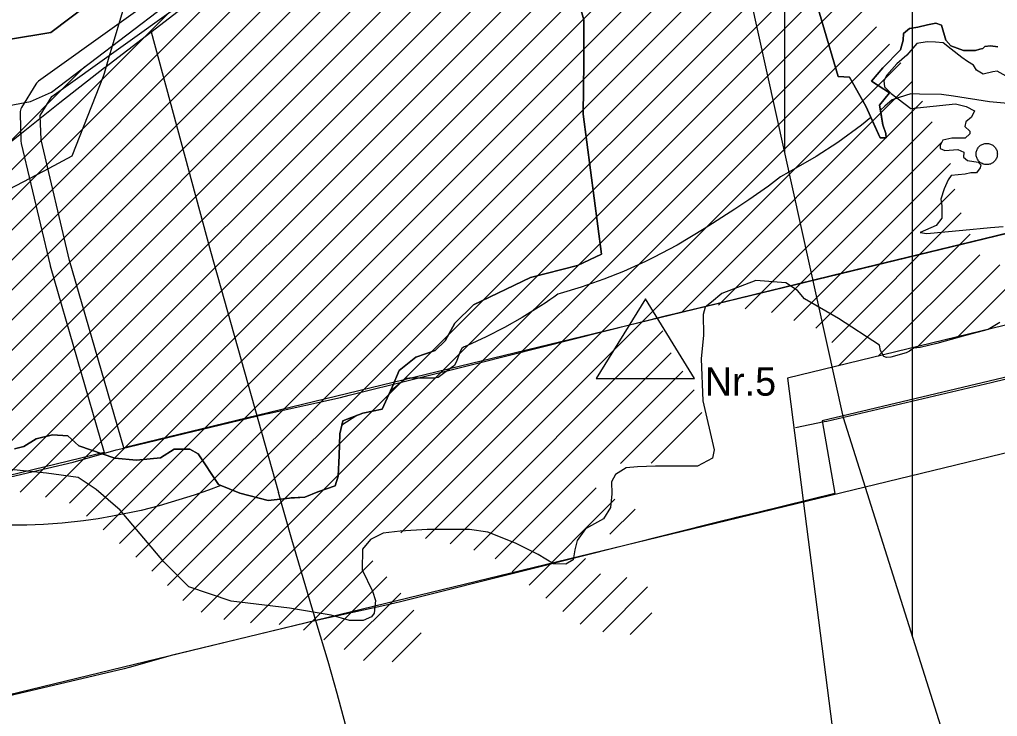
# Model space of a CAD drawing. Extents: x 468834 to 503362, y 294936 to 320859.
# Drawn here: x 481784 to 482703, y 305401 to 306056 of the extents above; entities that cross this region are included whole.
import ezdxf

# ---------------------------------------------------------------- set-up
doc = ezdxf.new("R2010")
doc.units = 0
for name, color, linetype in [('1020101_TIN11_plūdu riska teritorija', 7, 'Continuous'), ('1020103_TIN13_teritorijas ar augstu gruntsudens limeni', 7, 'Continuous'), ('1020700_TIN7_nacionalas_un_vietejas_nozimes_infrastrukturas_attistibas_teritorijas', 7, 'Continuous'), ('7311020201_par 1000 hektāriem lielākas dabiskas ūdenstilpes vides un dabas resursu aizsardzības aizsargjoslas teritorija lauku apvidos', 7, 'Continuous'), ('7311020400_applūstošā (10% applūduma varbūtība) teritorija', 7, 'Continuous'), ('7311090700_stingra režīma vides un dabas resursu aizsardzības aizsargjoslas teritorija ap pazemes ūdens ņemšanas vietu', 7, 'Continuous'), ('7312030301_ekspluatācijas aizsargjoslas teritorija gar valsts galvenajiem autoceļiem lauku apvidos', 7, 'Continuous'), ('7312070202_navigācijas tehniskā līdzekļa aviācijas gaisa kuģu lidojumu drošības nodrošināšanai tālās ietekmes zona', 7, 'Continuous'), ('7313040300_dabas lieguma dabas lieguma zonas teritorija', 7, 'Continuous'), ('7313040700_dabas lieguma sezonas lieguma teritorija', 7, 'Continuous'), ('aizkrāsojums-lidlauka tālās ietekmes zona', 7, 'Continuous'), ('aizkrāsojums-poldera teritorija', 7, 'Continuous'), ('aizkrāsojums_applūstošā teritorija', 7, 'Continuous'), ('Dabas lieguma robeža', 7, 'Continuous'), ('Koplietošanas novadgrāvis', 7, 'Continuous'), ('Polderu_baseini', 7, 'Continuous'), ('Potenciāli piesārņota vieta', 7, 'Continuous'), ('Teksts', 7, 'Continuous')]:
    doc.layers.add(name, color=color, linetype=linetype)

msp = doc.modelspace()

# ---------------------------------------------------------------- linework, layer by layer
at = {"layer": '1020101_TIN11_plūdu riska teritorija'}
for points in [[(482711.03, 306002.85), (482702.68, 306007.58), (482698.57, 306006.82), (482689.52, 306004.83), (482683.41, 306008.57), (482680.42, 306013.29), (482674.78, 306016.55), (482669.46, 306020.55), (482659.33, 306028.17), (482651.9, 306034.19), (482644.86, 306034.99), (482636.92, 306035.13), (482627.06, 306033.44), (482617.73, 306022.73), (482608.35, 306014.61), (482598.9, 306003.87), (482596.11, 305998.38), (482596.7, 305992.96), (482603, 305986.67), (482621.69, 305972.56), (482663.67, 305976.9), (482673.43, 305974.49), (482681.26, 305970.32), (482678.51, 305964.24), (482673.19, 305959.99), (482672.35, 305955.59), (482677.01, 305951.2), (482677.09, 305948.62), (482672.65, 305944.49), (482660.12, 305944.6), (482651.62, 305942.72), (482649.1, 305937.78), (482649.1, 305934.98), (482653.4, 305932.94), (482665.6, 305933.85), (482671.24, 305931.54), (482671.19, 305926.59), (482674.69, 305923.63), (482684.78, 305922.13), (482687.33, 305919.6), (482686.63, 305916.67), (482683.33, 305912.03), (482677.91, 305912.03), (482672.49, 305910.92), (482659.45, 305909.61), (482656.53, 305905.4), (482652.85, 305897.08), (482649.82, 305887.23), (482650.58, 305881.12), (482650.58, 305869.46), (482645.23, 305862.39), (482630.31, 305855.84), (482636.66, 305854.86), (482670.47, 305858.17), (482696.33, 305860.69), (482708.26, 305861.54)], [(482705.33, 305771.2), (482694.3, 305764.59), (482672.87, 305758.99), (482646.02, 305751.71), (482630.48, 305747.68), (482624.09, 305747.18), (482620.22, 305744.36), (482617.2, 305742.93), (482602.62, 305738.8), (482598.71, 305738.4), (482596.04, 305739.5), (482593.13, 305745.13), (482591.95, 305750.12), (482553.54, 305775.09), (482521.62, 305793.63), (482514.87, 305801.45), (482504.04, 305808.54), (482475.69, 305810.67), (482443.98, 305798.57), (482434.25, 305790.56), (482428.26, 305785.86), (482426.15, 305778.75), (482426.51, 305759.3), (482424.33, 305737.23), (482426, 305697.6), (482436.52, 305651.76), (482435.01, 305643.68), (482420.82, 305636.14), (482405.62, 305636.14), (482381.33, 305636.14), (482364.55, 305635.66), (482353.81, 305634.56), (482343.81, 305628.29), (482340.21, 305621.6), (482340.31, 305610.3), (482339.1, 305597.48), (482332.68, 305586.73), (482315.62, 305577.43), (482307.86, 305566.55), (482305.67, 305557.52), (482304.22, 305548.3), (482297.1, 305544.25), (482285.44, 305544.41), (482271.04, 305553.31), (482249.76, 305563.8), (482223.99, 305574.2), (482206.73, 305576.87), (482166.94, 305576.87), (482141.49, 305575.2), (482125.41, 305573.26), (482113.63, 305567.42), (482106.15, 305558.2), (482105.62, 305538.75), (482115.31, 305518.86), (482118.12, 305510.04), (482117.13, 305498.21), (482114.36, 305494.51), (482106.75, 305491.22), (482093.91, 305491.22), (482076.54, 305496.32), (482037.39, 305502.9), (481982.64, 305509.45), (481942.65, 305522.91), (481919.07, 305546.48), (481878.26, 305594.83), (481855.53, 305614.21), (481838.59, 305625.51), (481808.76, 305629.68), (481775.19, 305633.01)]]:
    msp.add_lwpolyline(points, dxfattribs=at)
at = {"layer": '1020103_TIN13_teritorijas ar augstu gruntsudens limeni'}
for p, q in [((481863.31, 306005.69), (481867.18, 306018.76)), ((481863.31, 306005.69), (481867.18, 306018.76)), ((481806.01, 305913.61), (481811.43, 305916.46)), ((481806.01, 305913.61), (481811.43, 305916.46))]:
    msp.add_line(p, q, dxfattribs=at)
for points in [[(481867.18, 306018.76), (481884.36, 306076.83), (481892.2, 306087.81)], [(481867.18, 306018.76), (481884.36, 306076.83), (481892.2, 306087.81)], [(481811.43, 305916.46), (481833.17, 305927.88), (481862.48, 306002.88), (481863.31, 306005.69)], [(481811.43, 305916.46), (481833.17, 305927.88), (481862.48, 306002.88), (481863.31, 306005.69)], [(481678.77, 305886.85), (481691.44, 305885.69), (481747.15, 305889.11), (481747.88, 305889.67), (481749.12, 305889.52), (481749.39, 305889.48), (481749.57, 305889.25), (481761, 305889.95), (481806.01, 305913.61)], [(481678.77, 305886.85), (481691.44, 305885.69), (481747.15, 305889.11), (481747.88, 305889.67), (481749.12, 305889.52), (481749.39, 305889.48), (481749.57, 305889.25), (481761, 305889.95), (481806.01, 305913.61)]]:
    msp.add_lwpolyline(points, dxfattribs=at)
at = {"layer": '1020700_TIN7_nacionalas_un_vietejas_nozimes_infrastrukturas_attistibas_teritorijas'}
for points in [[(481830.66, 305829.5), (481803.8, 305943.01), (481803.08, 305965.99), (481813.98, 305983.7), (482118.6, 306201.91), (482529.42, 306297.65), (482530.71, 306297.78), (482531.21, 306297.88), (482541.24, 306299.83), (482555.97, 306302.71), (482560.88, 306303.67), (482617.58, 306314.75), (482622.01, 306315.25), (482650.04, 306318.47), (482657.91, 306319.37), (482786.24, 306266.92)], [(481830.66, 305829.5), (481803.8, 305943.01), (481803.08, 305965.99), (481813.98, 305983.7), (482118.6, 306201.91), (482529.42, 306297.65), (482530.71, 306297.78), (482531.21, 306297.88), (482541.24, 306299.83), (482555.97, 306302.71), (482560.88, 306303.67), (482617.58, 306314.75), (482622.01, 306315.25), (482650.04, 306318.47), (482657.91, 306319.37), (482786.24, 306266.92)], [(482109.07, 306218.46), (481801.36, 305998.04), (481800.39, 305997.24), (481799.53, 305996.32), (481798.8, 305995.29), (481785.4, 305973.52), (481784.77, 305972.3), (481784.31, 305970.99), (481784.06, 305969.63), (481784, 305968.25), (481784.84, 305941.45), (481784.98, 305940.1), (481785.09, 305939.56), (481812.23, 305824.9), (481812.35, 305824.44), (481863.18, 305648.97), (481390.71, 305534.31)], [(482109.07, 306218.46), (481801.36, 305998.04), (481800.39, 305997.24), (481799.53, 305996.32), (481798.8, 305995.29), (481785.4, 305973.52), (481784.77, 305972.3), (481784.31, 305970.99), (481784.06, 305969.63), (481784, 305968.25), (481784.84, 305941.45), (481784.98, 305940.1), (481785.09, 305939.56), (481812.23, 305824.9), (481812.35, 305824.44), (481863.18, 305648.97), (481390.71, 305534.31)], [(482933.4, 305908.71), (481881.66, 305653.46), (481830.66, 305829.5)], [(482933.4, 305908.71), (481881.66, 305653.46), (481830.66, 305829.5)], [(481665.41, 305395.17), (482835.74, 305679.21)], [(481665.41, 305395.17), (482835.74, 305679.21)]]:
    msp.add_lwpolyline(points, dxfattribs=at)
at = {"layer": '7311020201_par 1000 hektāriem lielākas dabiskas ūdenstilpes vides un dabas resursu aizsardzības aizsargjoslas teritorija lauku apvidos'}
msp.add_lwpolyline([(482729.76, 305975.58), (482695.36, 305978.75), (482661.74, 305984.19), (482650.51, 305985.71), (482629.8, 305986.11), (482621.58, 305986.3), (482610.66, 305982.83), (482603.93, 305980.62), (482597.24, 305974.62), (482592.97, 305971.08), (482595.28, 305957.13), (482598.18, 305949.03), (482598.32, 305944.95), (482592.64, 305944.95), (482584.08, 305963.91), (482575.32, 305956.88), (482552.95, 305940.65), (482532.46, 305927.31), (482506.71, 305912.56), (482498.89, 305908.24), (482487.7, 305899.59), (482469.27, 305886.49), (482456.22, 305877.76), (482427.3, 305859.29), (482401.99, 305844.09), (482379.74, 305832.4), (482372.08, 305828.56), (482351.36, 305819.35), (482332.91, 305812.13), (482311.49, 305804.65), (482291.84, 305798.62), (482289.66, 305797.82), (482285.99, 305795.23), (482282.09, 305792.52), (482277.63, 305789.61), (482273.59, 305786.97), (482255.97, 305776.07), (482239.44, 305766.74), (482222.22, 305757.86), (482204.62, 305749.64), (482201.05, 305748.01), (482199.29, 305746.87), (482197.81, 305744.22), (482194.29, 305734.67), (482192.09, 305730.7), (482190.62, 305729.62), (482177, 305719.63), (482173.27, 305719), (482168.69, 305719), (482150.12, 305719), (482147.05, 305718.6), (482144.57, 305716.78), (482131.92, 305706.48), (482124.46, 305689.76), (482106.36, 305686.02), (482100.83, 305683.9), (482086.63, 305674.73), (482084.64, 305666.53), (482083.96, 305646.29), (482083.21, 305626.83), (482080.29, 305617.83), (482064.15, 305612.14), (482051.77, 305607.17), (482038.93, 305606.36), (482037.33, 305606.26), (482018.78, 305604.09), (482017.47, 305603.94), (481990.54, 305611), (481972.89, 305618.14), (481961.12, 305613.69), (481947.66, 305609), (481926.2, 305602.32), (481914.69, 305598.86), (481897.76, 305594.71), (481871.07, 305589.15), (481857.57, 305586.8), (481843.67, 305585), (481823.61, 305582.74), (481806.24, 305581.52), (481790.28, 305580.79), (481764.94, 305580.7)], dxfattribs=at)
at = {"layer": '7311020400_applūstošā (10% applūduma varbūtība) teritorija'}
for points in [[(482703.36, 306030.36), (482696.35, 306031.51), (482691.26, 306030.84), (482689.37, 306028.99), (482686.44, 306028.14), (482682.39, 306026.94), (482677.83, 306027.08), (482671.18, 306027.02), (482659.13, 306031.37), (482654.45, 306036.67), (482650.33, 306050.84), (482644.93, 306052.72), (482637.2, 306051.14), (482628.24, 306048.8), (482620.32, 306047.64), (482614.63, 306042.84), (482614.42, 306036.62), (482611.74, 306027.6), (482595.12, 306010.82), (482584.58, 305998.33), (482601.62, 305987.16), (482592.19, 305975.78), (482595.28, 305957.13), (482598.18, 305949.03), (482598.32, 305944.95), (482592.64, 305944.95), (482579.27, 305974.57), (482564.02, 306001.95), (482553.24, 306002.66), (482485.77, 306231.42)], [(482304.43, 306089.91), (482313.99, 306055.97), (482313.99, 306015.34), (482313.51, 305967.06), (482330.61, 305835.58), (482308.2, 305824.83), (482263.99, 305813.57), (482210.45, 305788.07), (482192.97, 305770.71), (482183.69, 305754.05), (482174.18, 305744.91), (482156.25, 305738.81), (482140.38, 305726.36), (482133.76, 305710.62), (482124.46, 305689.76), (482106.36, 305686.02), (482087.63, 305678.84), (482084.64, 305666.53), (482083.96, 305646.29), (482083.21, 305626.83), (482080.29, 305617.83), (482064.15, 305612.14), (482051.77, 305607.17), (482037.33, 305606.26), (482017.47, 305603.94), (481990.54, 305611), (481970.56, 305619.08), (481951.51, 305647.84), (481943.56, 305652.41), (481929.05, 305652.41), (481916.08, 305643.99), (481893.45, 305642.03), (481873.08, 305643.86), (481839.26, 305655.26), (481829.07, 305664.83), (481814.61, 305665.85), (481799.33, 305661.98), (481787.44, 305654.85), (481778.7, 305652.71)]]:
    msp.add_lwpolyline(points, dxfattribs=at)
at = {"layer": '7311090700_stingra režīma vides un dabas resursu aizsardzības aizsargjoslas teritorija ap pazemes ūdens ņemšanas vietu'}
msp.add_lwpolyline([(482702.91, 305929.71), (482702.87, 305928.84), (482702.76, 305927.97), (482702.57, 305927.12), (482702.31, 305926.29), (482701.97, 305925.48), (482701.57, 305924.71), (482701.1, 305923.97), (482700.57, 305923.28), (482699.98, 305922.64), (482699.34, 305922.05), (482698.65, 305921.52), (482697.91, 305921.05), (482697.14, 305920.65), (482696.33, 305920.31), (482695.5, 305920.05), (482694.65, 305919.86), (482693.78, 305919.75), (482692.91, 305919.71), (482692.04, 305919.75), (482691.17, 305919.86), (482690.32, 305920.05), (482689.49, 305920.31), (482688.68, 305920.65), (482687.91, 305921.05), (482687.17, 305921.52), (482686.48, 305922.05), (482685.84, 305922.64), (482685.25, 305923.28), (482684.72, 305923.97), (482684.25, 305924.71), (482683.85, 305925.48), (482683.51, 305926.29), (482683.25, 305927.12), (482683.06, 305927.97), (482682.95, 305928.84), (482682.91, 305929.71), (482682.95, 305930.58), (482683.06, 305931.45), (482683.25, 305932.3), (482683.51, 305933.13), (482683.85, 305933.94), (482684.25, 305934.71), (482684.72, 305935.45), (482685.25, 305936.14), (482685.84, 305936.78), (482686.48, 305937.37), (482687.17, 305937.9), (482687.91, 305938.37), (482688.68, 305938.77), (482689.49, 305939.11), (482690.32, 305939.37), (482691.17, 305939.56), (482692.04, 305939.67), (482692.91, 305939.71), (482693.78, 305939.67), (482694.65, 305939.56), (482695.5, 305939.37), (482696.33, 305939.11), (482697.14, 305938.77), (482697.91, 305938.37), (482698.65, 305937.9), (482699.34, 305937.37), (482699.98, 305936.78), (482700.57, 305936.14), (482701.1, 305935.45), (482701.57, 305934.71), (482701.97, 305933.94), (482702.31, 305933.13), (482702.57, 305932.3), (482702.76, 305931.45), (482702.87, 305930.58)], close=True, dxfattribs=at)
at = {"layer": '7312030301_ekspluatācijas aizsargjoslas teritorija gar valsts galvenajiem autoceļiem lauku apvidos'}
for points in [[(483411.74, 305886.23), (482538.33, 305678.85), (482549.99, 305610.47), (482477.55, 305592.8), (482456.06, 305587.55), (482455.26, 305587.36), (482441.16, 305584.05), (482263.15, 305539.15), (482141.83, 305508.87), (482132.41, 305506.52), (482130.45, 305506.05), (482129.71, 305505.88), (482061.12, 305490.77), (481927.41, 305458.67), (481886.53, 305447), (481881.91, 305445.8), (481831.56, 305434), (481693.81, 305401.61)], [(481647.17, 305596.1), (481785.84, 305628.7), (481833.93, 305639.98), (481874.55, 305651.57), (481878.85, 305652.7), (482015.34, 305685.46), (482016.43, 305685.72), (482017.17, 305685.89), (482085.32, 305700.9), (482093.4, 305702.92), (482214.48, 305733.13), (482393.02, 305778.17), (482394.59, 305778.55), (482409.07, 305781.96), (482430.15, 305787.1), (482559.44, 305818.63), (482677.18, 305847.12), (482727.6, 305859.22)]]:
    msp.add_lwpolyline(points, dxfattribs=at)
at = {"layer": '7312070202_navigācijas tehniskā līdzekļa aviācijas gaisa kuģu lidojumu drošības nodrošināšanai tālās ietekmes zona'}
msp.add_lwpolyline([(485919.77, 299448.94), (484759.97, 300960.42), (484056.87, 302064.06), (483452.63, 303224.79), (482951.86, 304433.76), (482558.36, 305681.78), (482275.13, 306959.34), (482104.33, 308256.73), (482047.25, 309564.06), (482104.33, 310871.4), (482275.13, 312168.79), (482558.36, 313446.35), (482951.86, 314694.37), (483452.63, 315903.34), (483846.7, 316660.32)], dxfattribs=at)
at = {"layer": '7313040300_dabas lieguma dabas lieguma zonas teritorija'}
msp.add_lwpolyline([(483262.45, 306442.89), (483166.01, 306341.72), (483118.73, 306397.51), (482845.46, 306301.06), (482660.12, 306396.56), (482578.8, 306371.03), (482483.3, 306354.01), (482166.53, 306269.85), (482094.67, 306254.72), (482009.57, 306192.32), (481812.89, 306043.86), (481773.17, 306037.24), (481710.77, 306102.49), (481645.52, 306141.25), (481387.38, 306316.19), (481144.25, 306369.79), (481040.27, 306354.7), (480542.98, 305757.35)], dxfattribs=at)
at = {"layer": '7313040700_dabas lieguma sezonas lieguma teritorija'}
msp.add_lwpolyline([(483262.45, 306442.89), (483166.01, 306341.72), (483150.95, 306359.48), (483147.69, 306363.33), (483118.73, 306397.51), (482845.46, 306301.06), (482660.12, 306396.56), (482578.8, 306371.03), (482483.3, 306354.01), (482166.53, 306269.85), (482094.67, 306254.72), (482009.57, 306192.32), (481812.89, 306043.86), (481773.17, 306037.24), (481710.77, 306102.49), (481645.52, 306141.25), (481387.38, 306316.19), (481144.25, 306369.79), (481040.27, 306354.7), (481043, 306665), (488335, 310490)], dxfattribs=at)
at = {"layer": 'aizkrāsojums-lidlauka tālās ietekmes zona'}
for p, q in [((482503.05, 305931.29), (482503.05, 310775.21)), ((482623.05, 305476.63), (482623.05, 310764.11))]:
    msp.add_line(p, q, dxfattribs=at)
at = {"layer": 'aizkrāsojums-poldera teritorija'}
for p, q in [((481892.98, 305550.83), (482663.32, 306321.18)), ((481877.56, 305563.7), (482630.91, 306317.05)), ((481907.95, 305537.52), (482682.48, 306312.06)), ((481846.55, 305589.26), (482559.93, 306302.64)), ((481862.05, 305576.48), (482595.42, 306309.85)), ((481922.81, 305524.1), (482701.65, 306302.94)), ((481830.47, 305601.47), (482524.44, 306295.43)), ((481936.95, 305509.96), (482720.81, 306293.81)), ((481807.85, 305607.13), (482488.95, 306288.22)), ((481954.23, 305498.95), (482739.97, 306284.69)), ((481758.18, 305614.03), (482417.96, 306273.81)), ((481784.29, 305611.85), (482453.45, 306281.02)), ((481975.72, 305492.15), (482759.14, 306275.57)), ((481723.99, 305608.12), (482382.47, 306266.6)), ((481687.87, 305600.29), (482346.98, 306259.4)), ((481629.31, 305570.01), (482311.49, 306252.19)), ((481585.07, 305582.34), (482240.51, 306237.77)), ((481607.86, 305576.85), (482276, 306244.98)), ((481501.8, 305527.35), (482205.01, 306230.57)), ((481469.16, 305522.99), (482169.52, 306223.36)), ((481446.04, 305528.16), (482134.03, 306216.15)), ((481423.12, 305533.52), (482082.25, 306192.65)), ((481400.2, 305538.89), (481963.46, 306102.15)), ((482000.78, 305488.94), (482583.18, 306071.33)), ((482027.52, 305487.39), (482589.42, 306049.29)), ((482141.94, 305573.52), (482601.54, 306033.12)), ((481382.71, 305549.69), (481844.66, 306011.64)), ((482165.14, 305568.43), (482612.14, 306015.44)), ((482405.84, 305780.86), (482622.43, 305997.44)), ((482440.8, 305787.53), (482632.51, 305979.24)), ((482465.83, 305784.28), (482641.55, 305960)), ((482490.58, 305780.74), (482650.6, 305940.76)), ((482511.47, 305773.35), (482658.93, 305920.81)), ((482532.31, 305765.9), (482662.96, 305896.56)), ((482547.13, 305752.43), (482669.01, 305874.32)), ((482553.47, 305730.5), (482677.49, 305854.51)), ((482590.87, 305739.61), (482686.33, 305835.07)), ((482628.26, 305748.72), (482705.18, 305825.64)), ((482665.66, 305757.83), (482727.38, 305819.55)), ((482188.34, 305563.35), (482388.43, 305763.44)), ((482210.53, 305557.27), (482396.22, 305742.95)), ((482230.86, 305549.31), (482407.12, 305725.57)), ((482348.67, 305638.83), (482417.72, 305707.88)), ((482377.33, 305639.21), (482424.94, 305686.82)), ((482246.72, 305536.88), (482325.71, 305615.87)), ((482262.58, 305524.46), (482343.26, 305605.14)), ((482338.67, 305572.27), (482362.37, 305595.96)), ((482050.46, 305482.04), (482115.84, 305547.42)), ((482278.45, 305512.04), (482315.76, 305549.35)), ((482069.81, 305473.11), (482128.89, 305532.19)), ((482294.31, 305499.62), (482329.88, 305535.19)), ((482310.69, 305487.72), (482354.62, 305531.65)), ((482331.9, 305480.64), (482374.09, 305522.83)), ((482088.86, 305463.88), (482141.94, 305516.95)), ((482106.85, 305453.59), (482154.19, 305500.93)), ((482357.69, 305478.15), (482378.08, 305498.53)), ((482134, 305452.45), (482161.26, 305479.71))]:
    msp.add_line(p, q, dxfattribs=at)
at = {"layer": 'aizkrāsojums_applūstošā teritorija'}
for points in [[(482485.77, 306231.42), (482553.24, 306002.66), (482564.02, 306001.95), (482579.27, 305974.57), (482592.64, 305944.95), (482598.32, 305944.95), (482598.18, 305949.03), (482595.28, 305957.13), (482592.19, 305975.78), (482601.62, 305987.16), (482584.58, 305998.33), (482595.12, 306010.82), (482611.74, 306027.6), (482614.42, 306036.62), (482614.63, 306042.84), (482620.32, 306047.64), (482628.24, 306048.8), (482637.2, 306051.14), (482644.93, 306052.72), (482650.33, 306050.84), (482654.45, 306036.67), (482659.13, 306031.37), (482671.18, 306027.02), (482677.83, 306027.08), (482682.39, 306026.94), (482686.44, 306028.14), (482689.37, 306028.99), (482691.26, 306030.84), (482696.35, 306031.51), (482703.36, 306030.36)], [(481778.7, 305652.71), (481787.44, 305654.85), (481799.33, 305661.98), (481814.61, 305665.85), (481829.07, 305664.83), (481839.26, 305655.26), (481873.08, 305643.86), (481893.45, 305642.03), (481916.08, 305643.99), (481929.05, 305652.41), (481943.56, 305652.41), (481951.51, 305647.84), (481970.56, 305619.08), (481990.54, 305611), (482017.47, 305603.94), (482037.33, 305606.26), (482051.77, 305607.17), (482064.15, 305612.14), (482080.29, 305617.83), (482083.21, 305626.83), (482083.96, 305646.29), (482084.64, 305666.53), (482087.63, 305678.84), (482106.36, 305686.02), (482124.46, 305689.76), (482133.76, 305710.62), (482140.38, 305726.36), (482156.25, 305738.81), (482174.18, 305744.91), (482183.69, 305754.05), (482192.97, 305770.71), (482210.45, 305788.07), (482263.99, 305813.57), (482308.2, 305824.83), (482330.61, 305835.58), (482313.51, 305967.06), (482313.99, 306015.34), (482313.99, 306055.97), (482304.43, 306089.91)]]:
    msp.add_lwpolyline(points, dxfattribs=at)
at = {"layer": 'Dabas lieguma robeža'}
msp.add_lwpolyline([(480542.98, 305757.35), (481040.27, 306354.7), (481144.25, 306369.79), (481387.38, 306316.19), (481645.52, 306141.25), (481710.77, 306102.49), (481773.17, 306037.24), (481812.89, 306043.86), (482009.57, 306192.32), (482094.67, 306254.72), (482166.53, 306269.85), (482483.3, 306354.01), (482578.8, 306371.03), (482660.12, 306396.56), (482845.46, 306301.06), (483118.73, 306397.51), (483166.01, 306341.72), (483262.45, 306442.89)], dxfattribs=at)
at = {"layer": 'Koplietošanas novadgrāvis'}
for points in [[(481769.74, 305936.84), (481821.31, 305978.13), (481821.36, 305978.17), (481821.41, 305978.21), (481863.56, 306010.95), (481863.58, 306010.97), (481863.61, 306010.99), (481906.98, 306044.23), (481978.82, 306099.8)], [(481907.25, 306044.44), (481963.11, 305838.28)], [(481963.11, 305838.28), (482027.02, 305611.64)], [(482854.68, 305753.18), (482697.01, 305714.68), (482542.6, 305678.36), (482540.12, 305677.85)], [(482540.12, 305677.85), (482513.21, 305672.24)], [(482094.37, 305377.21), (482082.12, 305422.62), (482073.72, 305452.81), (482063.46, 305486.94), (482039.66, 305567.45), (482027.02, 305611.64)]]:
    msp.add_lwpolyline(points, dxfattribs=at)
at = {"layer": 'Polderu_baseini'}
msp.add_lwpolyline([(480683.25, 305837.92), (481042.03, 306273.69), (481422.16, 306233.31), (481710.37, 306021.27), (481749.26, 305987.14), (481773.87, 305975.24), (481793.71, 305979.2), (481813.56, 305987.94), (482096.93, 306203.84), (482119.15, 306214.15), (482659.7, 306322.9), (482824.8, 306244.32), (482857.34, 306245.11), (483123.25, 306336.39), (483328.04, 306007.78), (483372.19, 305927.39), (482912.9, 305818.07), (482505.71, 305718.85), (482591.43, 305048.66), (482235.57, 304617.39)], dxfattribs=at)
at = {"layer": 'Potenciāli piesārņota vieta'}
for p, q in [((482372.05, 305793.49), (482325.8, 305718.76)), ((482418.3, 305718.76), (482372.05, 305793.49)), ((482325.8, 305718.76), (482418.3, 305718.76))]:
    msp.add_line(p, q, dxfattribs=at)

# ---------------------------------------------------------------- texts
at = {"layer": 'Teksts'}
msp.add_text('Nr.5', height=26.542, dxfattribs=at).set_placement((482427.85, 305702.55))

doc.saveas('drawing.dxf')
